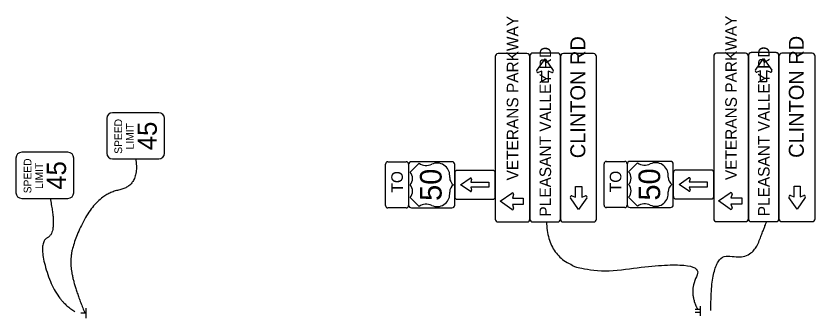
# Model space of a CAD drawing. Extents: x 1817563 to 1822411, y 498049 to 499279.
# Drawn here: x 1818099.9 to 1818359.4, y 499142.1 to 499240.3 of the extents above; entities that cross this region are included whole.
import ezdxf

# ---------------------------------------------------------------- set-up
doc = ezdxf.new("R2010")
doc.units = 0
doc.layers.add('PM_X_Stop_Line', color=7, linetype='Continuous')
doc.layers.add('SC_Scratch2', color=7, linetype='Continuous')

msp = doc.modelspace()

# ---------------------------------------------------------------- linework, layer by layer
at = {"layer": 'PM_X_Stop_Line'}
for p, q in [((1818269.03, 499222.58), (1818271.68, 499226.35)), ((1818271.68, 499226.35), (1818274.34, 499222.58)), ((1818270.69, 499222.37), (1818269.47, 499221.98)), ((1818270.69, 499222.36), (1818270.69, 499222.37)), ((1818270.69, 499218.85), (1818270.69, 499222.36)), ((1818273.9, 499221.98), (1818272.68, 499222.37)), ((1818272.68, 499218.85), (1818270.69, 499218.85)), ((1818219.88, 499178.68), (1818219.88, 499192.18)), ((1818220.63, 499192.93), (1818226.63, 499192.93)), ((1818227.38, 499192.18), (1818227.38, 499178.68)), ((1818230.78, 499192.46), (1818227.85, 499189.53)), ((1818242.38, 499189.36), (1818242.38, 499181.49)), ((1818254.76, 499190.11), (1818243.13, 499190.11)), ((1818254.76, 499190.11), (1818254.76, 499190.11)), ((1818255.51, 499181.49), (1818255.51, 499189.36)), ((1818240.74, 499187.77), (1818240.74, 499188.36)), ((1818244.26, 499185.43), (1818247.36, 499187.56)), ((1818247.84, 499187.21), (1818247.54, 499186.25)), ((1818247.54, 499186.25), (1818253.4, 499186.25)), ((1818253.4, 499186.25), (1818253.4, 499184.61)), ((1818247.32, 499183.33), (1818244.26, 499185.43)), ((1818253.4, 499184.61), (1818247.54, 499184.61)), ((1818247.54, 499184.61), (1818247.84, 499183.64)), ((1818281.6, 499184.93), (1818283.6, 499184.93)), ((1818283.6, 499184.93), (1818283.6, 499181.42)), ((1818227.85, 499181.32), (1818230.78, 499178.4)), ((1818240.74, 499182.5), (1818240.74, 499183.08)), ((1818257.09, 499180.06), (1818260.86, 499182.71)), ((1818261.45, 499182.28), (1818261.07, 499181.06)), ((1818264.59, 499181.06), (1818264.59, 499179.06)), ((1818282.6, 499177.43), (1818279.95, 499181.2)), ((1818280.39, 499181.8), (1818281.6, 499181.41)), ((1818285.25, 499181.2), (1818282.6, 499177.43)), ((1818283.6, 499181.41), (1818284.81, 499181.8)), ((1818283.6, 499181.42), (1818283.6, 499181.41)), ((1818243.13, 499180.74), (1818254.76, 499180.74)), ((1818260.86, 499177.41), (1818257.09, 499180.06)), ((1818261.08, 499179.06), (1818261.07, 499179.06)), ((1818261.07, 499179.06), (1818261.45, 499177.85)), ((1818264.59, 499179.06), (1818261.08, 499179.06)), ((1818226.63, 499177.93), (1818220.63, 499177.93)), ((1818122.51, 499145.29), (1818122.51, 499142.09)), ((1818322.03, 499144.85), (1818320.43, 499144.85)), ((1818322.03, 499145.97), (1818322.03, 499142.77)), ((1818122.51, 499143.69), (1818120.91, 499143.69)), ((1818322.03, 499143.89), (1818320.43, 499143.89)), ((1818322.03, 499144.37), (1818322.03, 499144.37)), ((1818322.03, 499144.37), (1818322.03, 499144.37))]:
    msp.add_line(p, q, dxfattribs=at)
for points in [[(1818265.82, 499228.1), (1818256.44, 499228.1)], [(1818275.76, 499228.3), (1818267.69, 499228.3)], [(1818287.46, 499228.11), (1818277.63, 499228.11)], [(1818255.51, 499227.16), (1818255.51, 499174.28)], [(1818266.76, 499227.36), (1818266.76, 499174.28)], [(1818266.76, 499174.28), (1818266.76, 499227.16)], [(1818276.7, 499174.28), (1818276.7, 499227.36)], [(1818276.7, 499227.17), (1818276.7, 499174.28)], [(1818288.4, 499174.28), (1818288.4, 499227.17)], [(1818272.68, 499222.36), (1818272.68, 499218.85)], [(1818129.35, 499206.98), (1818129.35, 499195.73)], [(1818146.23, 499208.85), (1818131.23, 499208.85)], [(1818148.1, 499195.73), (1818148.1, 499206.98)], [(1818131.23, 499193.85), (1818146.23, 499193.85)], [(1818227.38, 499191.99), (1818227.38, 499178.86)], [(1818241.44, 499192.93), (1818228.32, 499192.93)], [(1818242.38, 499178.86), (1818242.38, 499191.99)], [(1818281.6, 499181.42), (1818281.6, 499184.93)], [(1818261.08, 499181.06), (1818264.59, 499181.06)], [(1818228.32, 499177.93), (1818241.44, 499177.93)], [(1818256.44, 499173.34), (1818265.82, 499173.34)], [(1818267.69, 499173.34), (1818275.76, 499173.34)], [(1818277.63, 499173.34), (1818287.46, 499173.34)]]:
    msp.add_lwpolyline(points, dxfattribs=at)
for centre, radius, start, end in [((1818256.44, 499227.16), 0.938, 90, 180), ((1818265.82, 499227.16), 0.938, 360, 90), ((1818267.69, 499227.36), 0.938, 90, 180), ((1818275.76, 499227.36), 0.938, 360, 90), ((1818277.63, 499227.17), 0.938, 90, 180), ((1818287.46, 499227.17), 0.938, 360, 90), ((1818269.35, 499222.36), 0.389, 144.9207, 287.6378), ((1818274.02, 499222.36), 0.389, 252.3622, 35.0792), ((1818131.23, 499206.98), 1.88, 90, 180), ((1818146.23, 499206.98), 1.88, 0, 90), ((1818131.23, 499195.73), 1.88, 180, 270), ((1818146.23, 499195.73), 1.88, 270, 360), ((1818220.63, 499192.18), 0.75, 90, 180), ((1818226.63, 499192.18), 0.75, 0, 90), ((1818228.32, 499191.99), 0.938, 90, 180), ((1818233.13, 499195.82), 4.1, 234.9991, 295.4529), ((1818236.64, 499188.4), 4.1, 359.3617, 115.1681), ((1818241.44, 499191.99), 0.938, 0, 90), ((1818225.76, 499187.48), 2.93, 315.573, 44.427), ((1818243.13, 499189.36), 0.75, 90, 180), ((1818254.76, 499189.36), 0.75, 0, 90), ((1818243.67, 499187.77), 2.93, 180, 233.1301), ((1818247.54, 499187.3), 0.313, 342.7954, 124.5888), ((1818225.76, 499183.38), 2.93, 315.573, 44.427), ((1818243.67, 499183.08), 2.93, 126.8699, 180), ((1818247.54, 499183.55), 0.313, 224.9904, 17.2046), ((1818236.64, 499182.45), 4.1, 244.8319, 0.6383), ((1818243.13, 499181.49), 0.75, 180, 270), ((1818254.76, 499181.49), 0.75, 270, 0), ((1818261.08, 499182.4), 0.389, 342.3622, 125.0792), ((1818280.27, 499181.42), 0.389, 72.3622, 215.0792), ((1818284.93, 499181.42), 0.389, 324.9207, 107.6378), ((1818220.63, 499178.68), 0.75, 180, 270), ((1818226.63, 499178.68), 0.75, 270, 360), ((1818228.32, 499178.86), 0.938, 180, 270), ((1818233.13, 499175.04), 4.1, 64.5471, 125.0009), ((1818241.44, 499178.86), 0.938, 270, 360), ((1818261.08, 499177.73), 0.389, 234.9207, 17.6378), ((1818256.44, 499174.28), 0.938, 180, 270), ((1818265.82, 499174.28), 0.938, 270, 360), ((1818267.69, 499174.28), 0.938, 180, 270), ((1818275.76, 499174.28), 0.938, 270, 360), ((1818277.63, 499174.28), 0.938, 180, 270), ((1818287.46, 499174.28), 0.938, 270, 360)]:
    msp.add_arc(centre, radius, start, end, dxfattribs=at)
for points in [[(1818138.73, 499193.85), (1818140.14, 499185.11), (1818126.46, 499182.35), (1818117.36, 499165.15), (1818117.98, 499153.95), (1818122.27, 499143.69)], [(1818272.13, 499173.45), (1818272.68, 499154.5), (1818323.81, 499161.54), (1818318.18, 499150.36), (1818321.3, 499144.85)]]:
    msp.add_open_spline(points, degree=2, dxfattribs=at)
at = {"layer": 'SC_Scratch2'}
for p, q in [((1818340, 499222.69), (1818342.65, 499226.46)), ((1818342.65, 499226.46), (1818345.3, 499222.69)), ((1818341.65, 499222.48), (1818340.43, 499222.09)), ((1818341.65, 499222.46), (1818341.65, 499222.48)), ((1818341.65, 499218.96), (1818341.65, 499222.46)), ((1818344.86, 499222.09), (1818343.65, 499222.48)), ((1818343.65, 499218.96), (1818341.65, 499218.96)), ((1818290.84, 499178.79), (1818290.84, 499192.29)), ((1818291.59, 499193.04), (1818297.59, 499193.04)), ((1818298.34, 499192.29), (1818298.34, 499178.79)), ((1818301.74, 499192.57), (1818298.81, 499189.64)), ((1818313.34, 499189.47), (1818313.34, 499181.6)), ((1818325.72, 499190.22), (1818314.09, 499190.22)), ((1818325.72, 499190.22), (1818325.72, 499190.22)), ((1818326.47, 499181.6), (1818326.47, 499189.47)), ((1818311.7, 499187.88), (1818311.7, 499188.47)), ((1818315.22, 499185.54), (1818318.32, 499187.67)), ((1818318.8, 499187.32), (1818318.5, 499186.36)), ((1818318.5, 499186.36), (1818324.36, 499186.36)), ((1818324.36, 499186.36), (1818324.36, 499184.71)), ((1818318.28, 499183.44), (1818315.22, 499185.54)), ((1818324.36, 499184.71), (1818318.5, 499184.71)), ((1818318.5, 499184.71), (1818318.8, 499183.75)), ((1818352.56, 499185.04), (1818354.56, 499185.04)), ((1818354.56, 499185.04), (1818354.56, 499181.53)), ((1818298.81, 499181.43), (1818301.74, 499178.5)), ((1818311.7, 499182.61), (1818311.7, 499183.19)), ((1818328.05, 499180.17), (1818331.82, 499182.82)), ((1818332.42, 499182.39), (1818332.03, 499181.17)), ((1818335.55, 499181.17), (1818335.55, 499179.17)), ((1818353.56, 499177.54), (1818350.91, 499181.31)), ((1818351.35, 499181.9), (1818352.56, 499181.52)), ((1818356.21, 499181.31), (1818353.56, 499177.54)), ((1818354.56, 499181.52), (1818355.78, 499181.9)), ((1818354.56, 499181.53), (1818354.56, 499181.52)), ((1818314.09, 499180.85), (1818325.72, 499180.85)), ((1818331.82, 499177.52), (1818328.05, 499180.17)), ((1818332.05, 499179.17), (1818332.03, 499179.17)), ((1818332.03, 499179.17), (1818332.42, 499177.96)), ((1818335.55, 499179.17), (1818332.05, 499179.17)), ((1818297.59, 499178.04), (1818291.59, 499178.04))]:
    msp.add_line(p, q, dxfattribs=at)
for points in [[(1818336.78, 499228.21), (1818327.41, 499228.21)], [(1818346.72, 499228.41), (1818338.66, 499228.41)], [(1818358.42, 499228.22), (1818348.6, 499228.22)], [(1818326.47, 499227.27), (1818326.47, 499174.38)], [(1818337.72, 499227.47), (1818337.72, 499174.38)], [(1818337.72, 499174.38), (1818337.72, 499227.27)], [(1818347.66, 499174.38), (1818347.66, 499227.47)], [(1818347.66, 499227.28), (1818347.66, 499174.38)], [(1818359.36, 499174.38), (1818359.36, 499227.28)], [(1818343.65, 499222.46), (1818343.65, 499218.96)], [(1818099.87, 499194.12), (1818099.87, 499182.87)], [(1818116.75, 499196), (1818101.75, 499196)], [(1818118.62, 499182.87), (1818118.62, 499194.12)], [(1818298.34, 499192.1), (1818298.34, 499178.97)], [(1818312.41, 499193.04), (1818299.28, 499193.04)], [(1818313.34, 499178.97), (1818313.34, 499192.1)], [(1818352.56, 499181.53), (1818352.56, 499185.04)], [(1818101.75, 499181), (1818116.75, 499181)], [(1818332.05, 499181.17), (1818335.55, 499181.17)], [(1818299.28, 499178.04), (1818312.41, 499178.04)], [(1818327.41, 499173.45), (1818336.78, 499173.45)], [(1818338.66, 499173.45), (1818346.72, 499173.45)], [(1818348.6, 499173.45), (1818358.42, 499173.45)]]:
    msp.add_lwpolyline(points, dxfattribs=at)
for centre, radius, start, end in [((1818327.41, 499227.27), 0.938, 90, 180), ((1818336.78, 499227.27), 0.938, 360, 90), ((1818338.66, 499227.47), 0.938, 90, 180), ((1818346.72, 499227.47), 0.938, 360, 90), ((1818348.6, 499227.28), 0.938, 90, 180), ((1818358.42, 499227.28), 0.938, 360, 90), ((1818340.32, 499222.46), 0.389, 144.9207, 287.6378), ((1818344.98, 499222.46), 0.389, 252.3622, 35.0792), ((1818101.75, 499194.12), 1.88, 90, 180), ((1818116.75, 499194.12), 1.88, 0, 90), ((1818291.6, 499192.29), 0.75, 90, 180), ((1818297.6, 499192.29), 0.75, 0, 90), ((1818299.28, 499192.1), 0.938, 90, 180), ((1818304.1, 499195.93), 4.1, 234.9991, 295.4529), ((1818307.6, 499188.51), 4.1, 359.3617, 115.1681), ((1818312.41, 499192.1), 0.938, 0, 90), ((1818296.72, 499187.59), 2.93, 315.573, 44.427), ((1818314.1, 499189.47), 0.75, 90, 180), ((1818325.72, 499189.47), 0.75, 0, 90), ((1818314.63, 499187.88), 2.93, 180, 233.1301), ((1818318.5, 499187.41), 0.313, 342.7954, 124.5888), ((1818296.72, 499183.48), 2.93, 315.573, 44.427), ((1818314.63, 499183.19), 2.93, 126.8699, 180), ((1818318.5, 499183.66), 0.313, 224.9904, 17.2046), ((1818101.75, 499182.87), 1.88, 180, 270), ((1818116.75, 499182.87), 1.88, 270, 360), ((1818307.6, 499182.56), 4.1, 244.8319, 0.6383), ((1818314.1, 499181.6), 0.75, 180, 270), ((1818325.72, 499181.6), 0.75, 270, 0), ((1818332.05, 499182.51), 0.389, 342.3622, 125.0792), ((1818351.23, 499181.53), 0.389, 72.3622, 215.0792), ((1818355.89, 499181.53), 0.389, 324.9207, 107.6378), ((1818291.6, 499178.79), 0.75, 180, 270), ((1818297.6, 499178.79), 0.75, 270, 360), ((1818299.28, 499178.97), 0.938, 180, 270), ((1818304.1, 499175.14), 4.1, 64.5471, 125.0009), ((1818312.41, 499178.97), 0.938, 270, 360), ((1818332.05, 499177.84), 0.389, 234.9207, 17.6378), ((1818327.41, 499174.38), 0.938, 180, 270), ((1818336.78, 499174.38), 0.938, 270, 360), ((1818338.66, 499174.38), 0.938, 180, 270), ((1818346.72, 499174.38), 0.938, 270, 360), ((1818348.6, 499174.38), 0.938, 180, 270), ((1818358.42, 499174.38), 0.938, 270, 360)]:
    msp.add_arc(centre, radius, start, end, dxfattribs=at)
for points in [[(1818110.94, 499181), (1818113.38, 499169.82), (1818106.9, 499166.71), (1818112.93, 499147.57), (1818119.04, 499144.27)], [(1818325.54, 499144.58), (1818325.33, 499163.74), (1818338.71, 499160.71), (1818343.66, 499173.45), (1818343.66, 499173.45), (1818343.66, 499173.45)]]:
    msp.add_open_spline(points, degree=2, dxfattribs=at)

# ---------------------------------------------------------------- texts
at = {"layer": 'PM_X_Stop_Line'}
for s, height, p in [('VETERANS PARKWAY', 3.75, (1818263.01, 499186.85)), ('CLINTON RD', 4.857, (1818284.76, 499194.08)), ('PLEASANT VALLEY RD', 3.75, (1818273.65, 499175.09)), ('SPEED', 2.5, (1818134.35, 499195.52)), ('LIMIT', 2.5, (1818138.1, 499196.93)), ('45', 6.25, (1818145.6, 499196.67)), ('TO', 3.75, (1818225.51, 499182.92)), ('50', 7.031, (1818238.1, 499180.2))]:
    msp.add_text(s, height=height, rotation=90, dxfattribs=at).set_placement(p)
at = {"layer": 'SC_Scratch2'}
for s, height, p in [('VETERANS PARKWAY', 3.75, (1818333.97, 499186.96)), ('CLINTON RD', 4.857, (1818355.72, 499194.19)), ('PLEASANT VALLEY RD', 3.75, (1818344.61, 499175.2)), ('SPEED', 2.5, (1818104.88, 499182.67)), ('LIMIT', 2.5, (1818108.63, 499184.07)), ('45', 6.25, (1818116.13, 499183.82)), ('TO', 3.75, (1818296.47, 499183.03)), ('50', 7.031, (1818309.07, 499180.31))]:
    msp.add_text(s, height=height, rotation=90, dxfattribs=at).set_placement(p)

doc.saveas('drawing.dxf')
